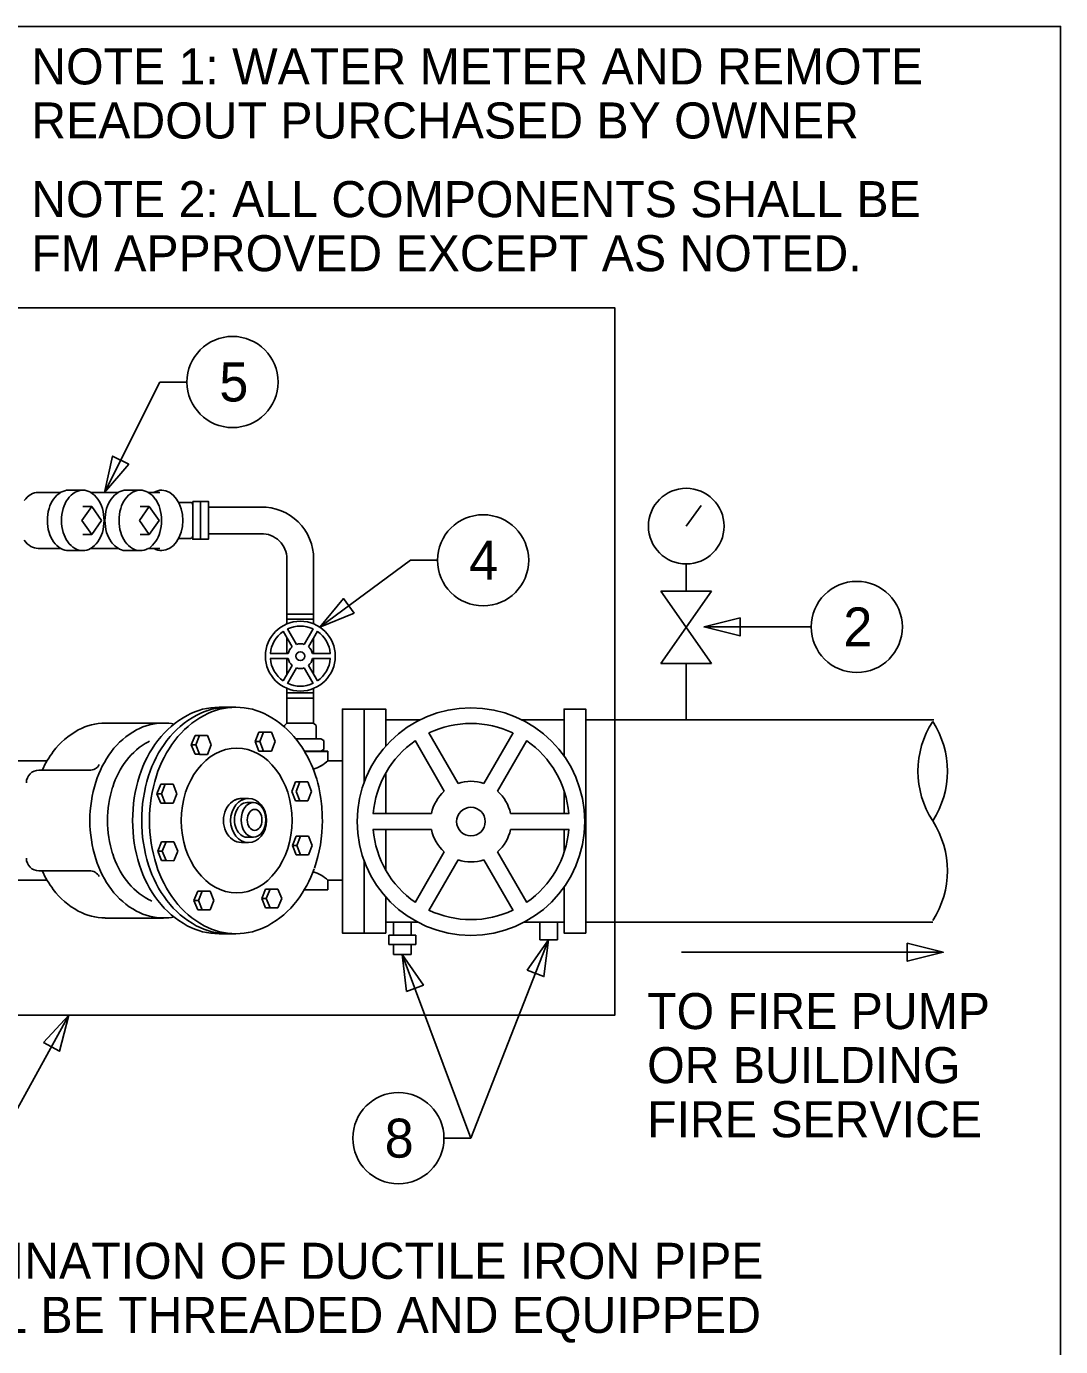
# Model space of a CAD drawing. Extents: x 10462 to 10511.2, y 10121.5 to 10170.9.
# Drawn here: x 10492.04 to 10511.16, y 10146.47 to 10170.89 of the extents above; entities that cross this region are included whole.
import ezdxf

# ---------------------------------------------------------------- set-up
doc = ezdxf.new("R2010")
doc.units = 0
for name, color, linetype in [('G-ANNO-NPLT', 7, 'Continuous'), ('G-ANNO-SYMB', 7, 'Continuous'), ('G-DETL-LINE', 7, 'Continuous'), ('G-DETL-TEXT', 7, 'Continuous')]:
    doc.layers.add(name, color=color, linetype=linetype)

msp = doc.modelspace()

# ---------------------------------------------------------------- linework, layer by layer
at = {"layer": 'G-ANNO-NPLT'}
msp.add_lwpolyline([(10462.021, 10170.89), (10511.163, 10170.89), (10511.163, 10125.39), (10462.021, 10125.39)], close=True, dxfattribs=at)
at = {"layer": 'G-ANNO-SYMB'}
for centre in [(10495.85, 10164.313), (10500.484, 10161.015), (10507.394, 10159.783), (10498.917, 10150.327)]:
    msp.add_circle(centre, 0.843, dxfattribs=at)
at = {"layer": 'G-DETL-LINE'}
for p, q in [((10493.482, 10162.271), (10494.508, 10164.313)), ((10495.008, 10164.313), (10494.508, 10164.313)), ((10492.253, 10162.271), (10492.674, 10162.271)), ((10492.82, 10162.312), (10493.081, 10162.312)), ((10493.233, 10162.271), (10493.227, 10162.271)), ((10493.227, 10162.271), (10493.738, 10162.271)), ((10493.884, 10162.312), (10494.144, 10162.312)), ((10494.297, 10162.271), (10494.29, 10162.271)), ((10494.29, 10162.271), (10494.505, 10162.271)), ((10493.063, 10161.753), (10493.247, 10162.012)), ((10493.247, 10162.012), (10493.081, 10162.012)), ((10493.247, 10162.012), (10493.43, 10161.753)), ((10494.127, 10161.753), (10494.31, 10162.012)), ((10494.31, 10162.012), (10494.144, 10162.012)), ((10494.31, 10162.012), (10494.493, 10161.753)), ((10495.071, 10162.087), (10494.854, 10162.087)), ((10495.113, 10161.464), (10495.113, 10162.045)), ((10495.113, 10162.042), (10495.113, 10162.045)), ((10495.404, 10162), (10496.376, 10162)), ((10504.24, 10161.647), (10504.516, 10162.027)), ((10493.063, 10161.753), (10493.247, 10161.494)), ((10493.247, 10161.494), (10493.43, 10161.753)), ((10494.127, 10161.753), (10494.31, 10161.494)), ((10494.31, 10161.494), (10494.493, 10161.753)), ((10493.247, 10161.494), (10493.081, 10161.494)), ((10494.31, 10161.494), (10494.144, 10161.494)), ((10495.071, 10161.419), (10494.854, 10161.419)), ((10495.113, 10161.461), (10495.113, 10161.464)), ((10495.404, 10161.506), (10496.376, 10161.506)), ((10492.253, 10161.235), (10492.674, 10161.235)), ((10492.82, 10161.195), (10493.081, 10161.195)), ((10493.443, 10161.235), (10493.227, 10161.235)), ((10493.227, 10161.235), (10493.738, 10161.235)), ((10493.827, 10161.195), (10494.144, 10161.195)), ((10494.29, 10161.235), (10494.505, 10161.235)), ((10496.857, 10161.041), (10496.857, 10159.84)), ((10497.35, 10161.041), (10497.35, 10159.84)), ((10497.465, 10159.779), (10499.141, 10161.015)), ((10499.641, 10161.015), (10499.141, 10161.015)), ((10504.24, 10160.947), (10504.24, 10160.443)), ((10504.709, 10159.104), (10503.772, 10160.443)), ((10503.772, 10160.443), (10504.709, 10160.443)), ((10504.709, 10160.443), (10503.772, 10159.104)), ((10497.35, 10160.022), (10496.857, 10160.022)), ((10496.787, 10159.703), (10496.953, 10159.415)), ((10497.35, 10159.925), (10496.857, 10159.925)), ((10496.864, 10159.748), (10497.03, 10159.46)), ((10497.177, 10159.46), (10497.343, 10159.748)), ((10497.255, 10159.415), (10497.421, 10159.703)), ((10504.571, 10159.783), (10506.551, 10159.783)), ((10496.857, 10159.581), (10496.857, 10159.289)), ((10497.35, 10159.581), (10497.35, 10159.289)), ((10496.547, 10159.289), (10496.879, 10159.289)), ((10497.328, 10159.289), (10497.66, 10159.289)), ((10496.547, 10159.198), (10496.879, 10159.198)), ((10496.787, 10158.784), (10496.953, 10159.071)), ((10496.857, 10159.198), (10496.857, 10158.906)), ((10496.864, 10158.739), (10497.03, 10159.027)), ((10497.177, 10159.027), (10497.343, 10158.739)), ((10497.255, 10159.071), (10497.421, 10158.784)), ((10497.328, 10159.198), (10497.66, 10159.198)), ((10497.35, 10159.198), (10497.35, 10158.906)), ((10503.772, 10159.104), (10504.709, 10159.104)), ((10504.24, 10159.104), (10504.24, 10158.064)), ((10496.857, 10158.647), (10496.857, 10158.465)), ((10496.857, 10158.647), (10496.857, 10158.004)), ((10497.35, 10158.562), (10496.857, 10158.562)), ((10497.35, 10158.647), (10497.35, 10158.465)), ((10497.35, 10158.647), (10497.35, 10158.004)), ((10495.601, 10158.297), (10495.913, 10158.297)), ((10497.35, 10158.465), (10496.857, 10158.465)), ((10497.881, 10158.239), (10497.881, 10156.203)), ((10493.463, 10158.005), (10494.572, 10158.006)), ((10496.857, 10158.004), (10496.813, 10157.96)), ((10496.857, 10158.004), (10497.35, 10158.004)), ((10497.35, 10158.004), (10497.394, 10157.96)), ((10498.682, 10158.063), (10499.313, 10158.063)), ((10501.206, 10158.063), (10501.981, 10158.063)), ((10502.381, 10158.064), (10508.817, 10158.064)), ((10495.088, 10157.601), (10495.157, 10157.775)), ((10495.241, 10157.775), (10495.157, 10157.775)), ((10495.172, 10157.601), (10495.241, 10157.775)), ((10495.241, 10157.775), (10495.386, 10157.775)), ((10495.456, 10157.601), (10495.386, 10157.775)), ((10496.27, 10157.662), (10496.339, 10157.836)), ((10496.424, 10157.836), (10496.339, 10157.836)), ((10496.354, 10157.662), (10496.424, 10157.836)), ((10496.424, 10157.836), (10496.569, 10157.835)), ((10496.639, 10157.662), (10496.569, 10157.835)), ((10496.813, 10157.96), (10496.813, 10157.929)), ((10497.394, 10157.96), (10497.394, 10157.716)), ((10500.02, 10156.89), (10499.479, 10157.827)), ((10501.039, 10157.827), (10500.498, 10156.89)), ((10495.157, 10157.427), (10495.088, 10157.601)), ((10495.172, 10157.601), (10495.088, 10157.601)), ((10495.241, 10157.427), (10495.172, 10157.601)), ((10495.386, 10157.426), (10495.456, 10157.601)), ((10496.339, 10157.487), (10496.27, 10157.662)), ((10496.354, 10157.662), (10496.27, 10157.662)), ((10496.424, 10157.487), (10496.354, 10157.662)), ((10496.569, 10157.487), (10496.639, 10157.662)), ((10497.017, 10157.716), (10497.482, 10157.716)), ((10497.54, 10157.682), (10497.482, 10157.716)), ((10497.54, 10157.517), (10497.482, 10157.483)), ((10497.54, 10157.517), (10497.54, 10157.682)), ((10499.766, 10156.744), (10499.225, 10157.681)), ((10501.293, 10157.681), (10500.752, 10156.744)), ((10491.572, 10157.308), (10492.422, 10157.308)), ((10495.241, 10157.427), (10495.157, 10157.427)), ((10495.386, 10157.426), (10495.241, 10157.426)), ((10496.424, 10157.487), (10496.339, 10157.487)), ((10496.569, 10157.487), (10496.424, 10157.487)), ((10497.178, 10157.483), (10497.613, 10157.483)), ((10497.179, 10157.482), (10497.614, 10157.482)), ((10497.613, 10157.483), (10497.613, 10157.308)), ((10497.614, 10157.482), (10497.614, 10157.308)), ((10497.614, 10157.308), (10497.881, 10157.308)), ((10492.271, 10157.133), (10493.216, 10157.133)), ((10494.453, 10156.699), (10494.522, 10156.873)), ((10494.606, 10156.873), (10494.522, 10156.873)), ((10494.537, 10156.699), (10494.606, 10156.873)), ((10494.606, 10156.873), (10494.751, 10156.872)), ((10494.821, 10156.699), (10494.751, 10156.872)), ((10496.944, 10156.741), (10497.013, 10156.915)), ((10497.097, 10156.915), (10497.013, 10156.915)), ((10497.028, 10156.741), (10497.097, 10156.915)), ((10497.097, 10156.915), (10497.242, 10156.915)), ((10497.312, 10156.741), (10497.242, 10156.915)), ((10494.522, 10156.524), (10494.453, 10156.699)), ((10494.537, 10156.699), (10494.453, 10156.699)), ((10494.606, 10156.524), (10494.537, 10156.699)), ((10494.751, 10156.524), (10494.821, 10156.699)), ((10496.015, 10156.61), (10496.147, 10156.61)), ((10496.114, 10156.534), (10496.238, 10156.534)), ((10497.013, 10156.566), (10496.944, 10156.741)), ((10497.097, 10156.566), (10497.013, 10156.566)), ((10497.097, 10156.566), (10497.028, 10156.741)), ((10497.242, 10156.566), (10497.097, 10156.566)), ((10497.242, 10156.566), (10497.312, 10156.741)), ((10494.606, 10156.524), (10494.522, 10156.524)), ((10494.751, 10156.524), (10494.606, 10156.524)), ((10499.528, 10156.332), (10498.445, 10156.332)), ((10502.073, 10156.332), (10500.991, 10156.332)), ((10494.467, 10155.634), (10494.536, 10155.808)), ((10494.621, 10155.808), (10494.536, 10155.808)), ((10494.551, 10155.634), (10494.621, 10155.808)), ((10494.621, 10155.808), (10494.766, 10155.808)), ((10494.836, 10155.634), (10494.766, 10155.808)), ((10496.015, 10155.795), (10496.147, 10155.795)), ((10496.114, 10155.894), (10496.238, 10155.894)), ((10496.956, 10155.742), (10497.026, 10155.916)), ((10497.11, 10155.916), (10497.026, 10155.916)), ((10497.041, 10155.742), (10497.11, 10155.916)), ((10497.11, 10155.916), (10497.255, 10155.915)), ((10497.325, 10155.742), (10497.255, 10155.915)), ((10499.528, 10156.034), (10498.445, 10156.034)), ((10502.073, 10156.034), (10500.991, 10156.034)), ((10494.551, 10155.634), (10494.467, 10155.634)), ((10494.536, 10155.46), (10494.467, 10155.634)), ((10494.621, 10155.46), (10494.551, 10155.634)), ((10494.766, 10155.459), (10494.836, 10155.634)), ((10497.041, 10155.742), (10496.956, 10155.742)), ((10497.026, 10155.567), (10496.956, 10155.742)), ((10497.11, 10155.567), (10497.026, 10155.567)), ((10497.11, 10155.567), (10497.041, 10155.742)), ((10497.255, 10155.567), (10497.11, 10155.567)), ((10497.255, 10155.567), (10497.325, 10155.742)), ((10499.766, 10155.623), (10499.225, 10154.685)), ((10501.293, 10154.685), (10500.752, 10155.623)), ((10494.621, 10155.46), (10494.536, 10155.46)), ((10494.766, 10155.459), (10494.621, 10155.46)), ((10500.02, 10155.476), (10499.479, 10154.539)), ((10501.039, 10154.539), (10500.498, 10155.476)), ((10491.572, 10155.097), (10492.422, 10155.097)), ((10492.271, 10155.272), (10493.216, 10155.272)), ((10497.614, 10154.923), (10497.614, 10155.097)), ((10497.614, 10155.097), (10497.881, 10155.097)), ((10495.136, 10154.724), (10495.206, 10154.898)), ((10495.29, 10154.898), (10495.206, 10154.898)), ((10495.221, 10154.724), (10495.29, 10154.898)), ((10495.29, 10154.898), (10495.435, 10154.897)), ((10495.505, 10154.724), (10495.435, 10154.897)), ((10496.391, 10154.76), (10496.46, 10154.934)), ((10496.544, 10154.934), (10496.46, 10154.934)), ((10496.475, 10154.76), (10496.544, 10154.934)), ((10496.544, 10154.934), (10496.689, 10154.934)), ((10496.759, 10154.76), (10496.689, 10154.934)), ((10497.179, 10154.923), (10497.614, 10154.923)), ((10495.206, 10154.549), (10495.136, 10154.724)), ((10495.221, 10154.724), (10495.136, 10154.724)), ((10495.29, 10154.549), (10495.221, 10154.724)), ((10495.435, 10154.549), (10495.505, 10154.724)), ((10496.46, 10154.585), (10496.391, 10154.76)), ((10496.475, 10154.76), (10496.391, 10154.76)), ((10496.544, 10154.585), (10496.46, 10154.585)), ((10496.544, 10154.585), (10496.475, 10154.76)), ((10496.689, 10154.585), (10496.544, 10154.585)), ((10496.689, 10154.585), (10496.759, 10154.76)), ((10493.497, 10154.399), (10494.572, 10154.399)), ((10495.29, 10154.549), (10495.206, 10154.549)), ((10495.435, 10154.549), (10495.29, 10154.549)), ((10495.913, 10154.108), (10495.601, 10154.108)), ((10498.682, 10154.323), (10499.275, 10154.323)), ((10498.827, 10154.079), (10498.827, 10154.323)), ((10499.152, 10154.323), (10499.152, 10154.079)), ((10501.243, 10154.323), (10501.981, 10154.323)), ((10501.532, 10154.323), (10501.532, 10153.997)), ((10501.857, 10153.997), (10501.857, 10154.323)), ((10502.381, 10154.324), (10508.798, 10154.324)), ((10498.739, 10154.079), (10499.24, 10154.079)), ((10498.739, 10154.079), (10498.739, 10153.911)), ((10498.739, 10154.079), (10498.739, 10154.079)), ((10498.739, 10153.911), (10499.24, 10153.911)), ((10498.739, 10153.911), (10498.739, 10153.911)), ((10498.827, 10153.726), (10498.827, 10153.911)), ((10499.152, 10153.911), (10499.152, 10153.726)), ((10499.24, 10154.079), (10499.24, 10153.911)), ((10499.24, 10154.079), (10499.24, 10154.079)), ((10499.24, 10153.911), (10499.24, 10153.911)), ((10501.532, 10153.997), (10501.857, 10153.997)), ((10499.152, 10153.726), (10498.827, 10153.726))]:
    msp.add_line(p, q, dxfattribs=at)
for points in [[(10493.93, 10162.792), (10493.482, 10162.271), (10493.632, 10162.942)], [(10495.113, 10162.104), (10495.258, 10162.104), (10495.258, 10161.406), (10495.113, 10161.406)], [(10495.258, 10162.104), (10495.404, 10162.104), (10495.404, 10161.406), (10495.258, 10161.406)], [(10498.1, 10160.04), (10497.465, 10159.779), (10497.902, 10160.308)], [(10505.237, 10159.95), (10504.571, 10159.783), (10505.237, 10159.616)]]:
    msp.add_lwpolyline(points, close=True, dxfattribs=at)
for points in [[(10498.282, 10156.904), (10498.282, 10158.265), (10497.881, 10158.265), (10497.881, 10154.12), (10498.282, 10154.12), (10498.282, 10155.462)], [(10498.682, 10157.577), (10498.682, 10158.265), (10498.282, 10158.265), (10498.282, 10156.904)], [(10501.981, 10154.972), (10501.981, 10154.12), (10502.381, 10154.12), (10502.381, 10158.265), (10501.981, 10158.265), (10501.981, 10157.394)], [(10498.682, 10156.332), (10498.682, 10157.08)], [(10501.981, 10156.755), (10501.981, 10156.332)], [(10498.682, 10155.286), (10498.682, 10156.034)], [(10501.981, 10156.034), (10501.981, 10155.611)], [(10498.282, 10155.462), (10498.282, 10154.12), (10498.682, 10154.12), (10498.682, 10154.789)]]:
    msp.add_lwpolyline(points, dxfattribs=at)
for centre, radius in [((10504.24, 10161.647), 0.7), ((10497.104, 10159.243), 0.646), ((10497.104, 10159.243), 0.0812), ((10500.259, 10156.183), 2.105), ((10500.259, 10156.183), 0.265)]:
    msp.add_circle(centre, radius, dxfattribs=at)
for centre, radius, start, end in [((10492.329, 10161.891), 0.401, 120.8869, 145.299), ((10492.253, 10162.018), 0.253, 90, 120.8869), ((10493.021, 10161.81), 0.587, 144.8243, 163.7257), ((10492.898, 10161.897), 0.436, 120.4433, 144.8243), ((10492.82, 10162.03), 0.282, 90, 120.4433), ((10493.282, 10161.81), 0.587, 144.8243, 163.7257), ((10493.159, 10161.897), 0.436, 120.4433, 144.8243), ((10493.081, 10162.03), 0.282, 90, 120.4433), ((10493.081, 10162.03), 0.282, 59.5567, 90), ((10493.003, 10161.897), 0.436, 35.1757, 59.5567), ((10493.556, 10161.897), 0.436, 120.4433, 120.9002), ((10492.88, 10161.81), 0.587, 16.2743, 35.1757), ((10494.085, 10161.81), 0.587, 144.8243, 163.7257), ((10493.962, 10161.897), 0.436, 120.4433, 144.8243), ((10493.884, 10162.03), 0.282, 90, 120.4433), ((10494.346, 10161.81), 0.587, 144.8243, 163.7257), ((10494.222, 10161.897), 0.436, 120.4433, 144.8243), ((10494.144, 10162.03), 0.282, 90, 120.4433), ((10494.144, 10162.03), 0.282, 59.5567, 90), ((10494.066, 10161.897), 0.436, 35.1757, 59.5567), ((10494.541, 10162.03), 0.282, 90, 120.4433), ((10493.943, 10161.81), 0.587, 16.2743, 35.1757), ((10493.216, 10161.753), 0.79, 163.7257, 180), ((10493.477, 10161.753), 0.79, 163.7257, 180), ((10492.685, 10161.753), 0.79, 0, 16.2743), ((10494.28, 10161.753), 0.79, 163.7257, 180), ((10494.541, 10161.753), 0.79, 163.7257, 180), ((10493.748, 10161.753), 0.79, 0, 16.2743), ((10495.071, 10162.045), 0.0419, 0, 90), ((10496.391, 10161.041), 0.959, 0, 90.904), ((10493.216, 10161.753), 0.79, 180, 196.2743), ((10493.477, 10161.753), 0.79, 180, 196.2743), ((10492.685, 10161.753), 0.79, 343.7257, 0), ((10494.28, 10161.753), 0.79, 180, 196.2743), ((10494.541, 10161.753), 0.79, 180, 196.2743), ((10493.748, 10161.753), 0.79, 343.7257, 0), ((10493.021, 10161.696), 0.587, 196.2743, 215.1757), ((10493.282, 10161.696), 0.587, 196.2743, 215.1757), ((10492.88, 10161.696), 0.587, 324.8243, 343.7257), ((10494.085, 10161.696), 0.587, 196.2743, 215.1757), ((10494.346, 10161.696), 0.587, 196.2743, 215.1757), ((10493.943, 10161.696), 0.587, 308.2266, 343.7257), ((10495.071, 10161.461), 0.0419, 270, 0), ((10496.391, 10161.041), 0.466, 0, 91.8624), ((10492.329, 10161.615), 0.401, 214.701, 239.1131), ((10492.253, 10161.488), 0.253, 239.1131, 270), ((10492.898, 10161.61), 0.436, 215.1757, 239.5567), ((10492.82, 10161.477), 0.282, 239.5567, 270), ((10493.159, 10161.61), 0.436, 215.1757, 239.5567), ((10493.081, 10161.477), 0.282, 239.5567, 270), ((10493.081, 10161.477), 0.282, 270, 300.4433), ((10493.003, 10161.61), 0.436, 300.4433, 324.8243), ((10493.962, 10161.61), 0.436, 215.1757, 252.046), ((10494.222, 10161.61), 0.436, 215.1757, 239.5567), ((10494.144, 10161.477), 0.282, 239.5567, 270), ((10494.144, 10161.477), 0.282, 270, 300.4433), ((10494.541, 10161.477), 0.282, 239.5567, 270), ((10497.104, 10159.243), 0.556, 124.6295, 175.2858), ((10497.104, 10159.243), 0.556, 64.6295, 115.3705), ((10497.104, 10159.243), 0.556, 4.7142, 55.3705), ((10497.104, 10159.243), 0.229, 71.3127, 108.6873), ((10497.104, 10159.243), 0.229, 131.3127, 168.4779), ((10497.104, 10159.243), 0.229, 11.5221, 48.6873), ((10497.104, 10159.243), 0.556, 184.7142, 235.3705), ((10497.104, 10159.243), 0.229, 191.5221, 228.6873), ((10497.104, 10159.243), 0.229, 251.3127, 288.6873), ((10497.104, 10159.243), 0.229, 311.3127, 348.4779), ((10497.104, 10159.243), 0.556, 304.6295, 355.2858), ((10497.104, 10159.243), 0.556, 244.6295, 295.3705), ((10495.601, 10157.063), 1.234, 90, 118.4823), ((10495.769, 10157.063), 1.234, 90, 118.4823), ((10495.913, 10157.063), 1.234, 90, 118.4823), ((10495.913, 10157.063), 1.234, 61.5177, 90), ((10493.497, 10156.969), 1.036, 90, 118.7905), ((10493.497, 10156.969), 1.036, 88.161, 90), ((10494.572, 10156.969), 1.036, 90, 118.7905), ((10495.826, 10156.649), 1.705, 118.4823, 142.6401), ((10494.572, 10156.969), 1.036, 79.0253, 90), ((10495.993, 10156.649), 1.705, 118.4823, 142.6401), ((10496.137, 10156.649), 1.705, 118.4823, 142.6401), ((10495.688, 10156.649), 1.705, 37.3599, 61.5177), ((10500.259, 10156.183), 1.814, 64.6295, 115.3705), ((10510.216, 10157.115), 1.691, 147.0136, 212.9864), ((10507.379, 10157.115), 1.691, 327.0136, 32.9864), ((10493.7, 10156.6), 1.458, 118.7905, 142.993), ((10494.774, 10156.6), 1.458, 118.7905, 142.993), ((10494.905, 10156.539), 1.277, 118.54, 142.7064), ((10496.179, 10156.379), 2.15, 142.6401, 162.4514), ((10494.735, 10156.852), 0.921, 117.1537, 118.54), ((10496.347, 10156.379), 2.15, 142.6401, 162.4514), ((10496.491, 10156.379), 2.15, 142.6401, 162.4514), ((10495.336, 10156.361), 2.159, 6.534, 37.7579), ((10500.259, 10156.183), 1.814, 124.6295, 175.2858), ((10500.259, 10156.183), 1.814, 4.7142, 55.3705), ((10494.019, 10156.36), 1.857, 142.993, 155.3864), ((10495.094, 10156.36), 1.857, 142.993, 162.661), ((10495.172, 10156.336), 1.613, 142.7064, 162.4909), ((10497.166, 10157.782), 0.652, 285.3257, 313.3274), ((10497.168, 10157.782), 0.651, 285.3257, 313.3274), ((10492.271, 10156.901), 0.233, 90, 180), ((10493.208, 10157.339), 0.206, 267.8882, 330.0944), ((10496.736, 10156.203), 2.734, 162.4514, 180), ((10496.904, 10156.203), 2.734, 162.4514, 180), ((10497.048, 10156.203), 2.734, 162.4514, 180), ((10495.597, 10156.203), 2.385, 162.661, 180), ((10495.594, 10156.203), 2.056, 162.4909, 180), ((10500.259, 10156.183), 0.746, 71.3127, 108.6873), ((10496.015, 10156.337), 0.273, 90, 116.9105), ((10496.147, 10156.337), 0.273, 90, 116.9105), ((10494.777, 10156.203), 2.734, 0, 8.5788), ((10500.259, 10156.183), 0.746, 131.3127, 168.4779), ((10500.259, 10156.183), 0.746, 11.5221, 48.6873), ((10495.597, 10156.203), 2.385, 180, 197.339), ((10495.594, 10156.203), 2.056, 180, 197.5091), ((10496.736, 10156.203), 2.734, 180, 197.5486), ((10496.904, 10156.203), 2.734, 180, 197.5486), ((10497.048, 10156.203), 2.734, 180, 197.5486), ((10494.777, 10156.203), 2.734, 341.1333, 0), ((10507.379, 10155.273), 1.691, 327.0136, 32.9864), ((10500.259, 10156.183), 1.814, 184.7142, 235.3705), ((10500.259, 10156.183), 0.746, 191.5221, 228.6873), ((10500.259, 10156.183), 0.746, 311.3127, 348.4779), ((10500.259, 10156.183), 1.814, 304.6295, 355.2858), ((10495.172, 10156.07), 1.613, 197.5091, 217.2936), ((10492.271, 10155.505), 0.233, 180, 270), ((10495.094, 10156.045), 1.857, 197.339, 217.007), ((10496.179, 10156.026), 2.15, 197.5486, 217.3599), ((10496.347, 10156.026), 2.15, 197.5486, 217.3599), ((10496.491, 10156.026), 2.15, 197.5486, 217.3599), ((10495.334, 10156.026), 2.15, 322.6401, 340.5399), ((10500.259, 10156.183), 0.746, 251.3127, 288.6873), ((10494.019, 10156.045), 1.857, 204.6136, 217.007), ((10493.208, 10155.066), 0.206, 29.9056, 92.1118), ((10494.905, 10155.866), 1.277, 217.2936, 241.46), ((10497.168, 10154.624), 0.651, 46.6726, 74.6743), ((10493.7, 10155.805), 1.458, 217.007, 241.2095), ((10494.774, 10155.805), 1.458, 217.007, 241.2095), ((10494.735, 10155.553), 0.921, 241.46, 246.0106), ((10495.826, 10155.756), 1.705, 217.3599, 241.5177), ((10495.993, 10155.756), 1.705, 217.3599, 241.5177), ((10496.137, 10155.756), 1.705, 217.3599, 241.5177), ((10495.688, 10155.756), 1.705, 298.4823, 322.6401), ((10493.497, 10155.436), 1.036, 241.2095, 270), ((10494.572, 10155.436), 1.036, 241.2095, 270), ((10494.572, 10155.436), 1.036, 270, 280.9747), ((10500.259, 10156.183), 1.814, 244.6295, 295.3705), ((10495.601, 10155.342), 1.234, 241.5177, 270), ((10495.769, 10155.342), 1.234, 241.5177, 270), ((10495.913, 10155.342), 1.234, 241.5177, 270), ((10495.913, 10155.342), 1.234, 270, 298.4823)]:
    msp.add_arc(centre, radius, start, end, dxfattribs=at)
for centre, major_axis, ratio, start_param, end_param in [((10494.541, 10161.753), (0, 0.558), 0.698111, 3.141593, 6.283185), ((10496.015, 10156.203), (0, 0.407), 0.816083, 0, 3.141593), ((10496.114, 10156.214), (0, 0.32), 0.707873, 0, 3.141593)]:
    msp.add_ellipse(centre, major_axis=major_axis, ratio=ratio, start_param=start_param, end_param=end_param, dxfattribs=at)
for centre, major_axis, ratio in [((10495.927, 10156.203), (0, 1.338), 0.766042), ((10496.147, 10156.203), (0, 0.407), 0.816083), ((10496.238, 10156.214), (0, 0.32), 0.711467), ((10496.259, 10156.214), (0, 0.195), 0.69425)]:
    msp.add_ellipse(centre, major_axis=major_axis, ratio=ratio, dxfattribs=at)
at = {"layer": 'G-DETL-TEXT'}
for p, q in [((10501.694, 10153.997), (10500.259, 10150.327)), ((10498.99, 10153.726), (10500.259, 10150.327)), ((10508.993, 10153.766), (10504.153, 10153.766)), ((10492.825, 10152.6), (10491.572, 10150.327)), ((10500.259, 10150.327), (10499.759, 10150.327))]:
    msp.add_line(p, q, dxfattribs=at)
for points in [[(10480.829, 10165.686), (10502.918, 10165.686), (10502.918, 10152.6), (10480.829, 10152.6)], [(10501.296, 10153.437), (10501.694, 10153.997), (10501.607, 10153.316)], [(10508.326, 10153.933), (10508.993, 10153.766), (10508.326, 10153.6)], [(10499.067, 10153.043), (10498.99, 10153.726), (10499.379, 10153.16)], [(10492.357, 10152.096), (10492.825, 10152.6), (10492.649, 10151.936)]]:
    msp.add_lwpolyline(points, close=True, dxfattribs=at)

# ---------------------------------------------------------------- texts
at = {"layer": 'G-ANNO-SYMB'}
for s, p in [('5', (10495.606, 10163.953)), ('4', (10500.225, 10160.655)), ('2', (10507.145, 10159.423)), ('8', (10498.664, 10149.967))]:
    msp.add_text(s, height=0.721, dxfattribs=at).set_placement(p)
at = {"layer": 'G-DETL-TEXT'}
for s, p in [('NOTE 1: WATER METER AND REMOTE', (10492.128, 10169.817)), ('READOUT PURCHASED BY OWNER', (10492.128, 10168.817)), ('NOTE 2: ALL COMPONENTS SHALL BE', (10492.128, 10167.362)), ('FM APPROVED EXCEPT AS NOTED.', (10492.128, 10166.362)), ('TO FIRE PUMP', (10503.517, 10152.345)), ('OR BUILDING', (10503.517, 10151.345)), ('FIRE SERVICE', (10503.517, 10150.345)), ('TERMINATION OF DUCTILE IRON PIPE', (10489.225, 10147.726)), ('SHALL BE THREADED AND EQUIPPED', (10489.225, 10146.726))]:
    msp.add_text(s, height=0.66667, dxfattribs=at).set_placement(p)

doc.saveas('drawing.dxf')
